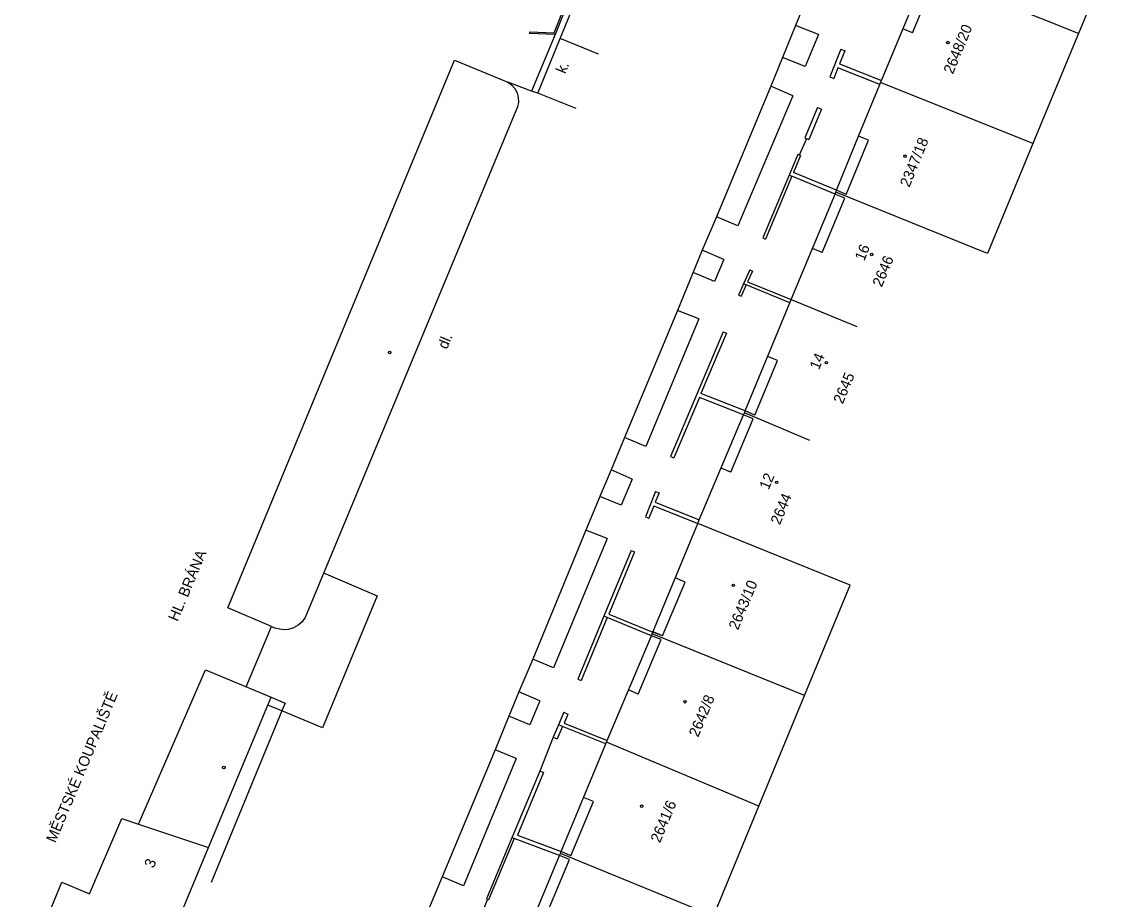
# Model space of a CAD drawing. Extents: x -584400 to -581602, y -1210894 to -1208793.
# Drawn here: x -583362 to -583284.5, y -1210695 to -1210633.2 of the extents above; entities that cross this region are included whole.
import ezdxf

# ---------------------------------------------------------------- set-up
doc = ezdxf.new("R2010")
doc.units = 0
for name, color, linetype in [('BUDOVY_MĚŘ', 7, 'Continuous'), ('BUDOVY_NEMĚŘ', 7, 'Continuous'), ('POMOC_POPIS', 7, 'Continuous'), ('ROZHRANÍ_PLOCH', 7, 'Continuous'), ('ZN_BUDOV', 7, 'Continuous'), ('ZN_DOPLŇKOVÉ', 7, 'Continuous'), ('Č_POPIS_EVID', 7, 'Continuous'), ('Č_POPIS_ORIENT', 7, 'Continuous')]:
    doc.layers.add(name, color=color, linetype=linetype)

msp = doc.modelspace()

# ---------------------------------------------------------------- linework, layer by layer
at = {"layer": 'BUDOVY_MĚŘ'}
for points in [[(-583301.58, -1210637.45), (-583301.52, -1210637.31), (-583298.43, -1210629.87), (-583298.37, -1210629.73)], [(-583331.57, -1210635.89), (-583327.82, -1210637.44), (-583327.55, -1210637.63), (-583327.32, -1210637.89), (-583327.16, -1210638.19), (-583327.08, -1210638.51), (-583327.07, -1210638.85), (-583327.14, -1210639.18), (-583342.07, -1210675.1), (-583342.29, -1210675.39), (-583342.56, -1210675.64), (-583342.89, -1210675.82), (-583343.24, -1210675.93), (-583343.61, -1210675.96), (-583343.98, -1210675.9), (-583344.17, -1210675.85)], [(-583303.13, -1210641.23), (-583301.64, -1210637.59), (-583301.58, -1210637.45)], [(-583304.74, -1210645.18), (-583304.68, -1210645.04), (-583303.13, -1210641.23)], [(-583307.88, -1210652.73), (-583304.79, -1210645.31), (-583304.74, -1210645.18)], [(-583306.55, -1210662.63), (-583311.17, -1210660.7), (-583311.11, -1210660.56), (-583307.97, -1210652.95), (-583307.88, -1210652.73), (-583303.26, -1210654.63)], [(-583314.44, -1210668.48), (-583314.34, -1210668.23), (-583311.23, -1210660.84), (-583311.17, -1210660.7)], [(-583317.65, -1210676.23), (-583317.61, -1210676.13), (-583314.44, -1210668.48)], [(-583344.44, -1210675.73), (-583344.17, -1210675.85)], [(-583320.86, -1210683.86), (-583320.81, -1210683.74), (-583317.71, -1210676.37), (-583317.65, -1210676.23)], [(-583349.08, -1210678.77), (-583344.47, -1210680.69)], [(-583355.51, -1210707.24), (-583348.87, -1210691.26), (-583344.69, -1210681.25), (-583344.47, -1210680.69)], [(-583324.11, -1210691.69), (-583324.05, -1210691.55), (-583320.91, -1210683.98), (-583320.86, -1210683.86)], [(-583327.29, -1210699.37), (-583327.26, -1210699.29), (-583324.17, -1210691.83), (-583324.11, -1210691.69)]]:
    msp.add_lwpolyline(points, dxfattribs=at)
at = {"layer": 'BUDOVY_NEMĚŘ'}
for points in [[(-583284.46, -1210626.29), (-583287.66, -1210634.02)], [(-583287.66, -1210634.02), (-583298.37, -1210629.73)], [(-583287.66, -1210634.02), (-583290.86, -1210641.76)], [(-583332.3, -1210637.64), (-583331.57, -1210635.89)], [(-583347.51, -1210674.41), (-583332.3, -1210637.64)], [(-583290.86, -1210641.76), (-583301.58, -1210637.45)], [(-583290.86, -1210641.76), (-583294.06, -1210649.49)], [(-583294.06, -1210649.49), (-583304.74, -1210645.18)], [(-583303.72, -1210672.82), (-583314.44, -1210668.48)], [(-583306.93, -1210680.58), (-583303.72, -1210672.82)], [(-583344.44, -1210675.73), (-583347.51, -1210674.41)], [(-583306.93, -1210680.58), (-583317.65, -1210676.23)], [(-583353.8, -1210689.63), (-583349.08, -1210678.77)], [(-583310.15, -1210688.36), (-583306.93, -1210680.58)], [(-583310.15, -1210688.36), (-583320.86, -1210683.86)], [(-583313.35, -1210696.1), (-583310.15, -1210688.36)], [(-583355.51, -1210707.24), (-583361.99, -1210704.37), (-583360.23, -1210700.2), (-583361.62, -1210699.63), (-583359.19, -1210693.72), (-583357.24, -1210694.52), (-583354.98, -1210689.24), (-583353.8, -1210689.63), (-583348.87, -1210691.26)], [(-583316.56, -1210703.85), (-583313.35, -1210696.1), (-583324.11, -1210691.69)]]:
    msp.add_lwpolyline(points, dxfattribs=at)
at = {"layer": 'ROZHRANÍ_PLOCH'}
for points in [[(-583324.12, -1210634.37), (-583313.75, -1210609.06), (-583305.65, -1210589.48)], [(-583299.34, -1210633.96), (-583297.75, -1210630.15), (-583298.42, -1210629.87)], [(-583306.53, -1210630.94), (-583307.56, -1210633.45)], [(-583307.56, -1210633.45), (-583308.48, -1210635.7)], [(-583305.96, -1210634.09), (-583307.56, -1210633.45)], [(-583299.34, -1210633.96), (-583300.01, -1210633.68)], [(-583324.47, -1210634.09), (-583326.15, -1210638.06)], [(-583325.71, -1210638.22), (-583324.12, -1210634.37)], [(-583321.44, -1210635.46), (-583324.12, -1210634.37)], [(-583305.96, -1210634.09), (-583306.9, -1210636.34), (-583308.48, -1210635.7)], [(-583308.48, -1210635.7), (-583309.3, -1210637.72)], [(-583326.15, -1210638.06), (-583327.82, -1210637.44)], [(-583309.3, -1210637.72), (-583313.14, -1210646.91)], [(-583307.76, -1210638.39), (-583309.3, -1210637.72)], [(-583325.71, -1210638.22), (-583326.15, -1210638.06)], [(-583323.01, -1210639.28), (-583325.71, -1210638.22)], [(-583307.76, -1210638.39), (-583311.62, -1210647.55), (-583313.14, -1210646.91)], [(-583304, -1210645.33), (-583302.44, -1210641.51), (-583303.13, -1210641.23)], [(-583305.69, -1210649.41), (-583304.11, -1210645.59), (-583304.8, -1210645.31)], [(-583304, -1210645.33), (-583304.68, -1210645.04)], [(-583313.14, -1210646.91), (-583314.13, -1210649.26)], [(-583314.13, -1210649.26), (-583315.88, -1210653.5)], [(-583312.62, -1210649.92), (-583314.13, -1210649.26)], [(-583305.69, -1210649.41), (-583306.38, -1210649.13)], [(-583312.62, -1210649.92), (-583313.26, -1210651.46), (-583314.78, -1210650.83)], [(-583315.88, -1210653.5), (-583319.59, -1210662.44)], [(-583314.37, -1210654.08), (-583318.1, -1210663.06), (-583319.59, -1210662.44)], [(-583314.37, -1210654.08), (-583315.88, -1210653.5)], [(-583310.43, -1210660.85), (-583308.84, -1210657.01), (-583309.52, -1210656.73)], [(-583312.11, -1210664.88), (-583310.54, -1210661.12), (-583311.23, -1210660.84)], [(-583310.43, -1210660.85), (-583311.11, -1210660.56)], [(-583319.59, -1210662.44), (-583320.53, -1210664.71)], [(-583320.53, -1210664.71), (-583321.33, -1210666.57)], [(-583319.06, -1210665.37), (-583320.53, -1210664.71)], [(-583312.11, -1210664.88), (-583312.81, -1210664.59)], [(-583319.06, -1210665.37), (-583319.83, -1210667.2), (-583321.33, -1210666.57)], [(-583321.33, -1210666.57), (-583322.32, -1210668.94)], [(-583322.32, -1210668.94), (-583326.06, -1210678.02)], [(-583320.81, -1210669.54), (-583324.6, -1210678.63), (-583326.06, -1210678.02)], [(-583320.81, -1210669.54), (-583322.32, -1210668.94)], [(-583340.77, -1210671.96), (-583337, -1210673.57), (-583340.86, -1210682.85), (-583343.7, -1210681.66)], [(-583316.92, -1210676.37), (-583315.34, -1210672.6), (-583316.03, -1210672.31)], [(-583318.63, -1210680.48), (-583317.03, -1210676.65), (-583317.71, -1210676.37)], [(-583316.92, -1210676.37), (-583317.61, -1210676.13)], [(-583316.92, -1210676.37), (-583317.59, -1210676.09)], [(-583326.06, -1210678.02), (-583327.03, -1210680.33)], [(-583327.03, -1210680.33), (-583327.74, -1210682.03)], [(-583325.57, -1210680.96), (-583327.03, -1210680.33)], [(-583318.63, -1210680.48), (-583319.32, -1210680.19)], [(-583343.7, -1210681.66), (-583344.69, -1210681.25)], [(-583344.47, -1210680.69), (-583343.47, -1210681.11), (-583343.7, -1210681.66)], [(-583325.57, -1210680.96), (-583326.26, -1210682.64), (-583327.74, -1210682.03)], [(-583343.7, -1210681.66), (-583348.69, -1210693.74)], [(-583327.74, -1210682.03), (-583328.71, -1210684.39)], [(-583328.71, -1210684.39), (-583332.43, -1210693.34)], [(-583327.23, -1210685), (-583328.71, -1210684.39)], [(-583327.23, -1210685), (-583330.92, -1210693.97), (-583332.43, -1210693.34)], [(-583323.37, -1210691.85), (-583321.78, -1210688.04), (-583322.48, -1210687.75)], [(-583325.09, -1210695.98), (-583323.48, -1210692.12), (-583324.17, -1210691.83)], [(-583323.37, -1210691.85), (-583324.05, -1210691.55)], [(-583323.37, -1210691.85), (-583324.05, -1210691.56)], [(-583332.43, -1210693.34), (-583333.5, -1210695.91)]]:
    msp.add_lwpolyline(points, dxfattribs=at)
at = {"layer": 'ZN_BUDOV'}
for centre in [(-583296.85, -1210634.65), (-583299.87, -1210642.64), (-583302.21, -1210649.56), (-583336.12, -1210656.45), (-583305.4, -1210657.17), (-583308.89, -1210665.59), (-583311.94, -1210672.83), (-583315.35, -1210681.02), (-583347.79, -1210685.64), (-583318.4, -1210688.36)]:
    msp.add_circle(centre, 0.0875, dxfattribs=at)
at = {"layer": 'ZN_DOPLŇKOVÉ'}
for points in [[(-583317.32, -1210615.8), (-583317.2, -1210615.85), (-583324.47, -1210634.09), (-583326.28, -1210634.02)], [(-583326.28, -1210633.89), (-583324.56, -1210633.96), (-583317.32, -1210615.8)], [(-583326.28, -1210633.89), (-583326.28, -1210634.02)], [(-583304.38, -1210635.12), (-583305.16, -1210637.06), (-583304.88, -1210637.17)], [(-583304.38, -1210635.12), (-583304.1, -1210635.23), (-583304.47, -1210636.14)], [(-583304.47, -1210636.14), (-583301.52, -1210637.31)], [(-583301.64, -1210637.59), (-583304.58, -1210636.42), (-583304.88, -1210637.17)], [(-583306.03, -1210639.22), (-583306.92, -1210641.36), (-583306.64, -1210641.48)], [(-583305.75, -1210639.34), (-583306.64, -1210641.48)], [(-583306.03, -1210639.22), (-583305.75, -1210639.34)], [(-583306.79, -1210641.42), (-583307.32, -1210642.56)], [(-583307.22, -1210642.6), (-583307.4, -1210642.52), (-583308.02, -1210643.98)], [(-583307.22, -1210642.6), (-583307.72, -1210643.79)], [(-583308.02, -1210643.98), (-583309.87, -1210648.39), (-583309.68, -1210648.47)], [(-583307.83, -1210644.06), (-583309.68, -1210648.47)], [(-583308.02, -1210643.98), (-583307.83, -1210644.06)], [(-583304.79, -1210645.31), (-583307.83, -1210644.06)], [(-583304.68, -1210645.04), (-583307.72, -1210643.79)], [(-583310.78, -1210650.64), (-583311.22, -1210651.62)], [(-583310.78, -1210650.64), (-583310.6, -1210650.72), (-583310.94, -1210651.47)], [(-583311.22, -1210651.62), (-583311.57, -1210652.41), (-583311.39, -1210652.49)], [(-583311.04, -1210651.69), (-583311.39, -1210652.49)], [(-583311.04, -1210651.69), (-583311.22, -1210651.62)], [(-583307.97, -1210652.95), (-583311.04, -1210651.69)], [(-583310.94, -1210651.47), (-583307.88, -1210652.73)], [(-583312.65, -1210655), (-583316.37, -1210663.76), (-583316.13, -1210663.86)], [(-583312.65, -1210655), (-583312.43, -1210655.09), (-583314.23, -1210659.33)], [(-583311.23, -1210660.84), (-583314.32, -1210659.61), (-583316.13, -1210663.86)], [(-583311.11, -1210660.56), (-583314.23, -1210659.33)], [(-583317.42, -1210666.22), (-583318.13, -1210668), (-583317.89, -1210668.1)], [(-583317.42, -1210666.22), (-583317.17, -1210666.32), (-583317.44, -1210666.99)], [(-583317.54, -1210667.23), (-583317.89, -1210668.1)], [(-583317.54, -1210667.23), (-583314.44, -1210668.48)], [(-583317.44, -1210666.99), (-583314.34, -1210668.23)], [(-583319.14, -1210670.38), (-583321.05, -1210675)], [(-583318.9, -1210670.48), (-583320.71, -1210674.86), (-583317.61, -1210676.13)], [(-583319.14, -1210670.38), (-583318.9, -1210670.48)], [(-583321.05, -1210675), (-583322.89, -1210679.43), (-583322.65, -1210679.53)], [(-583320.81, -1210675.1), (-583322.65, -1210679.53)], [(-583320.81, -1210675.1), (-583321.05, -1210675)], [(-583317.71, -1210676.37), (-583320.81, -1210675.1)], [(-583346.22, -1210679.96), (-583344.44, -1210675.73)], [(-583323.86, -1210681.76), (-583324.24, -1210682.65)], [(-583323.86, -1210681.76), (-583323.58, -1210681.88), (-583323.85, -1210682.52)], [(-583324.24, -1210682.65), (-583324.61, -1210683.52), (-583324.33, -1210683.63)], [(-583323.96, -1210682.76), (-583324.33, -1210683.63)], [(-583323.96, -1210682.76), (-583324.24, -1210682.65)], [(-583320.91, -1210683.98), (-583323.96, -1210682.76)], [(-583323.85, -1210682.52), (-583320.81, -1210683.74)], [(-583324.61, -1210683.52), (-583325.56, -1210685.89)], [(-583325.29, -1210686), (-583325.56, -1210685.89), (-583327.52, -1210690.58)], [(-583325.29, -1210686), (-583327.12, -1210690.4), (-583324.05, -1210691.55)], [(-583327.52, -1210690.58), (-583329.32, -1210694.88), (-583329.16, -1210694.95)], [(-583327.36, -1210690.64), (-583329.16, -1210694.95)], [(-583327.36, -1210690.64), (-583327.52, -1210690.58)], [(-583324.17, -1210691.83), (-583327.36, -1210690.64)], [(-583329.24, -1210694.91), (-583330.18, -1210697.23)]]:
    msp.add_lwpolyline(points, dxfattribs=at)

# ---------------------------------------------------------------- texts
at = {"layer": 'POMOC_POPIS'}
for s, rotation, p in [('k.', 67.55642, (-583323.77, -1210636.89)), ('dl.', 67.55642, (-583332.09, -1210656.27)), ('HL. BRÁNA', 67.2178, (-583351.05, -1210675.42)), ('MĚSTSKÉ KOUPALIŠTĚ', 67.21998, (-583359.64, -1210690.99))]:
    msp.add_text(s, height=0.75, rotation=rotation, dxfattribs=at).set_placement(p)
at = {"layer": 'Č_POPIS_EVID'}
for s, rotation, p in [('16', 67.51397, (-583302.74, -1210650.07)), ('2646', 67.32019, (-583301.5, -1210651.9)), ('14', 67.34231, (-583305.92, -1210657.72)), ('2645', 67.32019, (-583304.25, -1210660.12)), ('12', 67.34025, (-583309.46, -1210666.16)), ('2644', 67.32019, (-583308.67, -1210668.62)), ('3', 67.37428, (-583352.73, -1210692.77))]:
    msp.add_text(s, height=0.75, rotation=rotation, dxfattribs=at).set_placement(p)
at = {"layer": 'Č_POPIS_ORIENT'}
for s, rotation, p in [('2648/20', 67.44578, (-583296.5, -1210636.92)), ('2347/18', 67.80188, (-583299.56, -1210644.88)), ('2643/10', 67.32002, (-583311.62, -1210676.02)), ('2642/8', 67.32002, (-583314.42, -1210683.56)), ('2641/6', 67.32002, (-583317.11, -1210690.99))]:
    msp.add_text(s, height=0.75, rotation=rotation, dxfattribs=at).set_placement(p)

doc.saveas('drawing.dxf')
